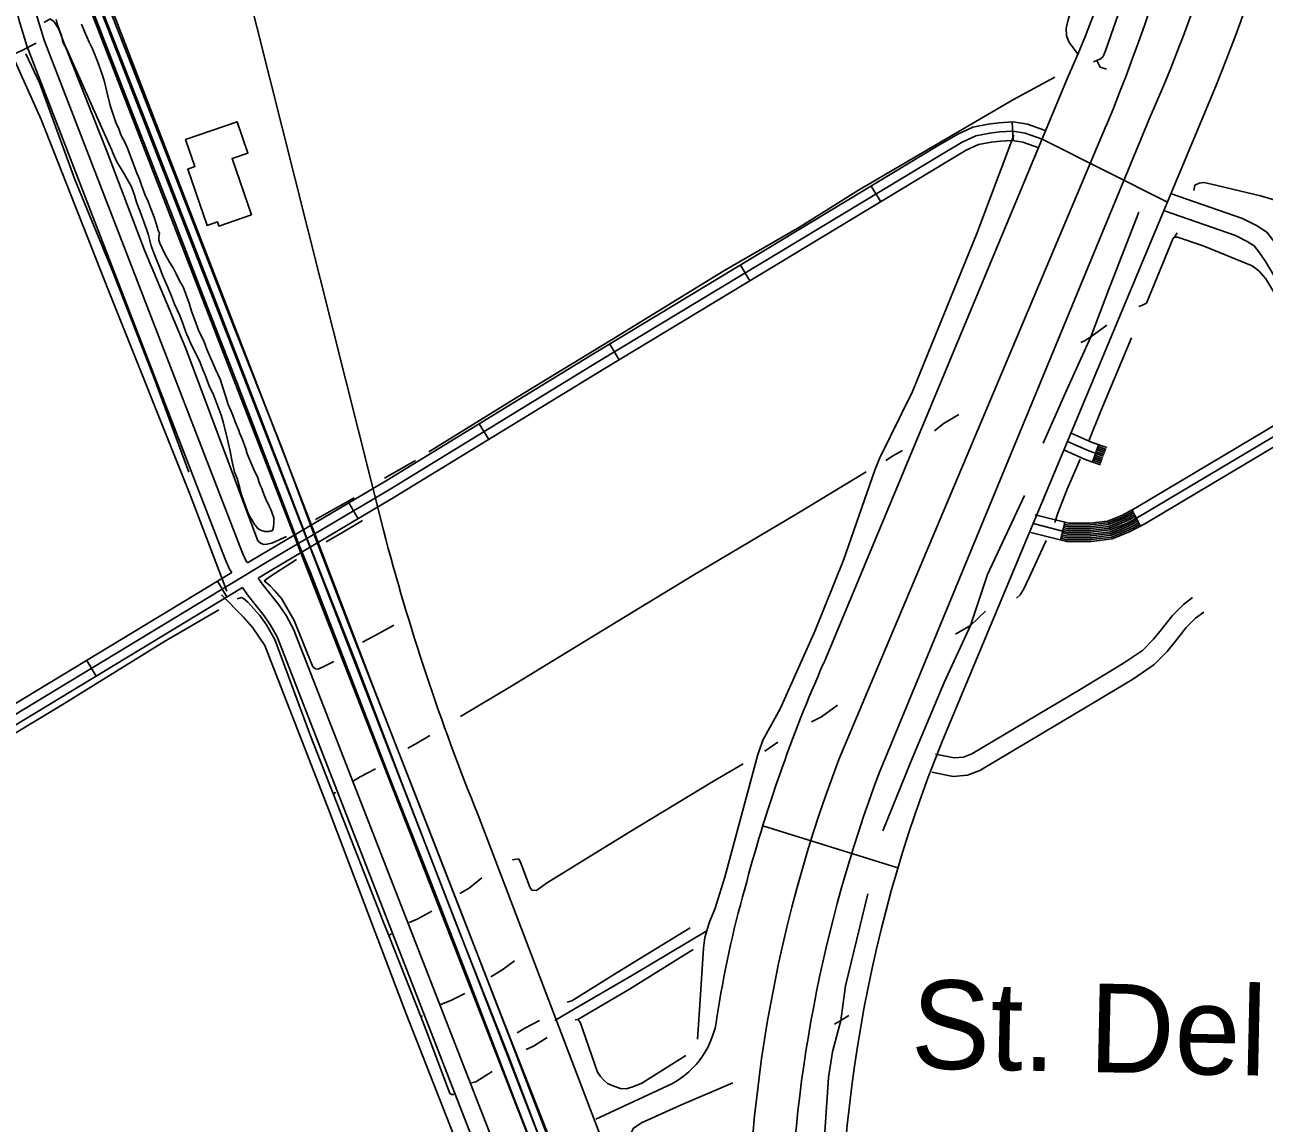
# Model space of a CAD drawing. Extents: x 3297753 to 3335611, y 652252 to 677623.
# Drawn here: x 3302520 to 3304548, y 670038 to 671835 of the extents above; entities that cross this region are included whole.
import ezdxf

# ---------------------------------------------------------------- set-up
doc = ezdxf.new("R2010")
doc.units = 0
for name, color, linetype in [('V-BLDG-OTLN', 7, 'Continuous'), ('V-DTCH-CNTR', 7, 'Continuous'), ('V-RAIL-TRAK', 7, 'Continuous'), ('V-ROAD-CNTR', 7, 'Continuous'), ('V-SITE-VEGE', 7, 'Continuous'), ('V-TOPO-GNAM-IDEN', 7, 'Continuous'), ('V-TOPO-SHOR', 7, 'Continuous')]:
    doc.layers.add(name, color=color, linetype=linetype)

msp = doc.modelspace()

# ---------------------------------------------------------------- linework, layer by layer
at = {"layer": 'V-BLDG-OTLN'}
msp.add_lwpolyline([(3302891.2, 671523.9), (3302859.4, 671615.8), (3302885.3, 671624.8), (3302867.7, 671675.9), (3302783.4, 671646.8), (3302798.6, 671602.6), (3302786.9, 671598.6), (3302818.7, 671506.3), (3302835.6, 671512.1), (3302837.8, 671505.5)], close=True, dxfattribs=at)
at = {"layer": 'V-DTCH-CNTR'}
for points in [[(3304244.1, 671785.6), (3304229, 671805.8), (3304224.6, 671816.7), (3304224.2, 671829.1), (3304227.2, 671843), (3304299.5, 672078.6), (3304340.8, 672243.1), (3304357.6, 672327.6), (3304367.6, 672385.1), (3304397.4, 672611.9), (3304404.4, 672725.7), (3304402.5, 672766.3), (3304397.4, 672822.7), (3304381.7, 672886.3), (3304375.8, 672900.6), (3304371.5, 672908), (3304359.4, 672920.7), (3304308.5, 672964), (3304301.4, 672972.1), (3304283.9, 672998.3)], [(3301862.2, 671467.5), (3302180.1, 671631), (3302468.1, 671771), (3302499.7, 671785.3), (3302515.6, 671792.4), (3302539, 671804.8)], [(3302499.7, 671785.3), (3302546.9, 671679.9), (3302657.1, 671400), (3302789.5, 671068.5), (3302850.9, 670908.2)], [(3304138.6, 671653.9), (3304078, 671493.1), (3303972.7, 671234.6), (3303918.8, 671125), (3303911.1, 671106.2), (3303859.7, 670958.7), (3303813.6, 670843.8), (3303756.1, 670715.5), (3303728, 670664.4), (3303721.6, 670647), (3303719.8, 670640.8), (3303665.8, 670440.3), (3303649.4, 670388.1), (3303640.4, 670367.2), (3303636, 670352.2), (3303632.9, 670341.5), (3303630.7, 670324.3), (3303624.5, 670231.2), (3303620.6, 670175.3)], [(3302842.1, 670902.3), (3302878.3, 670865.5), (3302893.3, 670848.1), (3302912.7, 670819), (3303018.6, 670547.3), (3303144, 670216.9), (3303265.4, 669907.8), (3303395.9, 669571.4), (3303462.9, 669403.2), (3303542.7, 669195.5), (3303547.3, 669180.4), (3303546.6, 669157), (3303533, 669058.1), (3303521.6, 669013)], [(3303636, 670352.2), (3303514.3, 670279.8), (3303420.9, 670225.4), (3303387.2, 670205.9)]]:
    msp.add_lwpolyline(points, dxfattribs=at)
at = {"layer": 'V-RAIL-TRAK'}
for points in [[(3302181.6, 673057.5), (3302229.8, 672933.1), (3302296.9, 672759.3), (3302374.4, 672560.5), (3302455, 672349.9), (3302535.3, 672147.1), (3302633.7, 671892), (3302728.1, 671651.1), (3302827.9, 671394.2), (3302937.3, 671109.7), (3302983.3, 670990.7), (3303061.7, 670791.9), (3303137.8, 670593.1), (3303225.7, 670365.7), (3303312.1, 670146.1), (3303400.2, 669915.1), (3303477.6, 669717.2), (3303551.6, 669527.1), (3303640.5, 669300.6), (3303710.4, 669119), (3303794.8, 668900.7), (3303880.9, 668677)], [(3303865.6, 668760.1), (3303793, 668948.4), (3303739.8, 669084.6), (3303721.9, 669124.8), (3303683.6, 669226.5), (3303609, 669421.9), (3303553, 669563.5), (3303502.7, 669694.7), (3303411, 669924.2), (3303320.1, 670159.8), (3303237.1, 670375.8), (3303155.6, 670584.1), (3303054.9, 670841.4), (3302995, 670997.5), (3302940.6, 671142.8), (3302854.9, 671358.3), (3302764.3, 671592.4), (3302665.5, 671843.8), (3302574.2, 672074.7), (3302480.7, 672320.3), (3302400.5, 672534.1), (3302313.6, 672755.6), (3302230.6, 672970.7), (3302196.1, 673060.4)], [(3303841.3, 668740.2), (3303767.3, 668931.7), (3303710.7, 669076.9), (3303696.6, 669112.1), (3303647.9, 669236.5), (3303572.8, 669433.9), (3303556.4, 669476.2), (3303519.6, 669571), (3303477.1, 669674.8), (3303404, 669864.5), (3303320.1, 670079.2), (3303246.5, 670271.6), (3303180.4, 670443.7), (3303116.4, 670604.7), (3303055.8, 670762.2), (3302987.7, 670938.8), (3302969.9, 670981.8), (3302932.6, 671079), (3302866.5, 671251), (3302811.4, 671392.1), (3302762.7, 671518.7), (3302691.1, 671703.9), (3302618.1, 671892.7)]]:
    msp.add_lwpolyline(points, dxfattribs=at)
at = {"layer": 'V-ROAD-CNTR'}
for p, q in [((3304137.4, 671645.7), (3304135.7, 671675.6)), ((3303920.6, 671545.2), (3303905.1, 671570.9)), ((3303706.7, 671415.9), (3303691.1, 671441.6)), ((3303492.7, 671286.7), (3303477.2, 671312.4)), ((3303279.4, 671156.3), (3303263.8, 671181.9)), ((3304277.2, 671147.6), (3304267, 671119.4)), ((3303065.5, 671026.6), (3303050.2, 671052.4)), ((3304331.5, 671041), (3304345.8, 671014.6)), ((3304222.1, 671020.9), (3304214.7, 670991.8)), ((3302850.9, 670898.7), (3302835.3, 670924.3)), ((3302637, 670769.2), (3302621.5, 670794.9))]:
    msp.add_line(p, q, dxfattribs=at)
for points in [[(3303107, 671007.8), (3302817.6, 672159), (3302659.4, 672783.7), (3302407.6, 673804.4), (3302220.1, 674556.3), (3302197.1, 674662.2)], [(3303929.7, 668588.8), (3303721.8, 669127.7), (3303498.9, 669709), (3303308.4, 670192.2), (3303092.6, 670746.3), (3302990.7, 671011.8), (3302616.9, 671979.1), (3302395, 672548.1), (3302140.6, 673200.8), (3301941.7, 673724), (3301858.4, 673934.7)], [(3306005.5, 663196.3), (3304715.5, 666525.6), (3304323.1, 667532.4), (3303700.3, 669143.4), (3302983.3, 670989.4), (3302517.9, 672183.2), (3302128.4, 673187.7), (3301925.1, 673723.4), (3301858.5, 673891.5)], [(3301858.5, 673843), (3302110.4, 673192.6), (3302969.1, 670977.7), (3303699.5, 669104.9), (3304312.1, 667521.8), (3304841.2, 666157.3), (3305391.9, 664734.2), (3306004.5, 663141.9)], [(3301853.3, 672053.9), (3302344.2, 672280.1), (3302370.6, 672286), (3302388.1, 672281.1), (3302400.7, 672272.5), (3302410.8, 672259.5), (3302424, 672232.3), (3302519.1, 671985.6), (3302526.7, 671962.8), (3302531.2, 671932.8), (3302534.3, 671904.9), (3302535.6, 671867.9), (3302539.6, 671851), (3302552, 671809.8), (3302875.9, 670971.9), (3302881.4, 670959.2), (3302884.8, 670954.3)], [(3301865.8, 672026.6), (3302353.8, 672251.5), (3302369.8, 672255.1), (3302375.2, 672253.6), (3302379.9, 672250.4), (3302385.2, 672243.6), (3302396.5, 672220.4), (3302490.9, 671975.5), (3302497.4, 671955.8), (3302501.4, 671928.9), (3302504.3, 671902.7), (3302505.7, 671863.9), (3302510.6, 671843.3), (3302523.6, 671800), (3302848.1, 670960.5), (3302855.1, 670944.4), (3302859.1, 670938.7)], [(3304226.8, 671748.8), (3303827.3, 670790.5)], [(3304468.9, 671734.1), (3304022.2, 670665)], [(3304189.6, 671661.7), (3304160.6, 671672), (3304137.6, 671675.8), (3304114.1, 671674.4), (3304096.5, 671672.3), (3304071.5, 671667.3), (3304046.8, 671656), (3304014.9, 671637.2), (3303452.5, 671297.5), (3303110.4, 671088), (3302907.3, 670967.9), (3302884.8, 670954.3)], [(3304359.7, 671680.4), (3303917.6, 670609.2)], [(3304184.6, 671647.5), (3304156.8, 671657.4), (3304136.8, 671660.7), (3304115.4, 671659.5), (3304098.9, 671657.5), (3304076.1, 671652.9), (3304053.8, 671642.7), (3304022.6, 671624.3), (3303460.3, 671284.7), (3303118.1, 671075.2), (3302915, 670955), (3301860.5, 670316.7)], [(3304289.7, 671669.7), (3303852.2, 670632.6)], [(3304179.6, 671633.4), (3304153.1, 671642.8), (3304136, 671645.6), (3304116.7, 671644.5), (3304101.3, 671642.7), (3304080.8, 671638.6), (3304060.7, 671629.4), (3304030.3, 671611.4), (3303468.1, 671271.8), (3303125.9, 671062.3), (3302922.7, 670942.2), (3302902, 670929.6)], [(3304389.8, 671544.6), (3304184.6, 671647.5)], [(3304814.2, 671065), (3304575.3, 671463.7), (3304565.3, 671478.7), (3304552.5, 671495.3), (3304535.3, 671506.4), (3304512.8, 671517.7), (3304394.7, 671558.8)], [(3304672.3, 671243.5), (3304550, 671447.6), (3304540.9, 671461.2), (3304531.9, 671472.9), (3304520.4, 671480.4), (3304501.1, 671490.1), (3304384.8, 671530.5)], [(3304169.9, 671018.6), (3304226.7, 671004.2), (3304264.1, 671004.6), (3304295.5, 671008.3), (3304322.6, 671019.1), (3304345.5, 671031.5), (3304692.9, 671238.3)], [(3304173.6, 671033.1), (3304228.5, 671019.3), (3304263.1, 671019.5), (3304291.7, 671022.9), (3304316.2, 671032.7), (3304338.1, 671044.6), (3304672.3, 671243.5)], [(3304166.3, 671004), (3304224.9, 670989.2), (3304265.1, 670989.6), (3304299.2, 670993.6), (3304329, 671005.5), (3304352.9, 671018.5), (3304687.7, 671217.7)], [(3304232.1, 671166.6), (3304266.4, 671151.5), (3304290.4, 671142.9)], [(3304226, 671152.9), (3304260.9, 671137.6), (3304285.3, 671128.8)], [(3304276.2, 671144.8), (3304289.4, 671140)], [(3304220, 671139.1), (3304255.3, 671123.7), (3304280.1, 671114.7)], [(3304269.1, 671125.1), (3304282.2, 671120.3)], [(3304270.1, 671127.9), (3304283.2, 671123.1)], [(3304271.1, 671130.7), (3304284.2, 671125.9)], [(3304272.1, 671133.5), (3304285.3, 671128.8)], [(3304273.2, 671136.3), (3304286.3, 671131.6)], [(3304274.2, 671139.2), (3304287.3, 671134.4)], [(3304275.2, 671142), (3304288.3, 671137.2)], [(3304268, 671122.2), (3304281.2, 671117.5)], [(3304216.9, 671000.5), (3304226, 670998.2), (3304264.5, 670998.6), (3304296.9, 671002.4), (3304325.2, 671013.7), (3304341.5, 671022.5)], [(3304217.7, 671003.4), (3304226.3, 671001.2), (3304264.3, 671001.6), (3304296.2, 671005.4), (3304323.9, 671016.4), (3304340.1, 671025.2)], [(3304218.4, 671006.3), (3304226.7, 671004.2), (3304264.1, 671004.6), (3304295.5, 671008.3), (3304322.6, 671019.1), (3304338.6, 671027.8)], [(3304219.1, 671009.2), (3304227, 671007.2), (3304263.9, 671007.5), (3304294.7, 671011.2), (3304321.3, 671021.9), (3304337.2, 671030.5)], [(3304219.9, 671012.1), (3304227.4, 671010.2), (3304263.7, 671010.5), (3304294, 671014.2), (3304320.1, 671024.6), (3304335.8, 671033.1)], [(3304220.6, 671015.1), (3304227.8, 671013.2), (3304263.5, 671013.5), (3304293.2, 671017.1), (3304318.8, 671027.3), (3304334.4, 671035.7)], [(3304221.4, 671018), (3304228.1, 671016.3), (3304263.3, 671016.5), (3304292.5, 671020), (3304317.5, 671030), (3304332.9, 671038.4)], [(3304215.5, 670994.7), (3304225.2, 670992.2), (3304264.9, 670992.6), (3304298.4, 670996.6), (3304327.7, 671008.3), (3304344.4, 671017.3)], [(3304216.2, 670997.6), (3304225.6, 670995.2), (3304264.7, 670995.6), (3304297.7, 670999.5), (3304326.4, 671011), (3304342.9, 671019.9)], [(3302859.1, 670938.7), (3301860.5, 670334.2)], [(3302902, 670929.6), (3302908.6, 670920.3), (3302935.9, 670885.8), (3302947.7, 670868.5), (3302960.1, 670846.1), (3303638.4, 669105)], [(3302876.3, 670914.1), (3301860.5, 670299.2)], [(3302876.3, 670914.1), (3302884.5, 670902.4), (3302911.7, 670868), (3302922.1, 670852.7), (3302932.9, 670833.4), (3303612.4, 669089.2)], [(3304430.7, 670897.7), (3304416.1, 670886.4), (3304398, 670868.6), (3304379.5, 670845.1), (3304367.1, 670829.6), (3304348.8, 670811.1), (3304318, 670790.1), (3304247, 670747.5), (3304069.7, 670641.8), (3304056.1, 670636.5), (3304041, 670635.4), (3304010, 670641.5)], [(3304449.1, 670874), (3304435.9, 670863.8), (3304420.4, 670848.5), (3304403, 670826.5), (3304389.5, 670809.7), (3304368.1, 670787.9), (3304334.2, 670764.8), (3304262.4, 670721.8), (3304082.9, 670614.8), (3304062.9, 670607), (3304039.2, 670605.2), (3304004.2, 670612.1)], [(3303526.3, 669848.3), (3303261.8, 670541.9)], [(3303727.6, 670524), (3303948.8, 670455.5)], [(3303579, 670102.1), (3303454.4, 670044.5)]]:
    msp.add_lwpolyline(points, dxfattribs=at)
for centre, radius, start, end in [((3301923.9, 672761.6), 2665, 336.0643, 356.8078), ((3301815.2, 672812.6), 2864.5, 337.8829, 356.1146), ((3301352.1, 672880.3), 3177.3, 337.6024, 354.4678), ((3301948, 672750.8), 2489.4, 336.2654, 354.3553), ((3306797.6, 671975.8), 3815.5, 194.6969, 202.0738), ((3306054.5, 669805.5), 2435.3, 156.1423, 165.3625), ((3306144.2, 669804.4), 2289.9, 157.9226, 184.037), ((3305997.7, 669817.5), 2295.2, 159.1973, 184.4635), ((3306068.5, 669801.1), 2297.7, 159.4088, 179.1328), ((3305328.3, 669958.2), 1694.5, 164.1527, 171.4384), ((3303509.3, 670228.7), 144.6, 298.84, 352.7293)]:
    msp.add_arc(centre, radius, start, end, dxfattribs=at)
at = {"layer": 'V-SITE-VEGE'}
for points in [[(3302895.2, 671107.3), (3302901.7, 671093.4), (3302903.2, 671087.3), (3302906.1, 671080.7), (3302908, 671075.9), (3302911.3, 671066.8), (3302914.7, 671058.9), (3302920.8, 671046.3), (3302922.7, 671042), (3302927.5, 671028), (3302927.7, 671020.5), (3302927, 671013), (3302925.5, 671007.2), (3302919.3, 671005.7), (3302913.2, 671005.5), (3302906, 671008), (3302901.5, 671010.9), (3302895.1, 671018.7), (3302893.7, 671021.3), (3302887.2, 671031.7), (3302884.8, 671038.7), (3302878.6, 671054.8), (3302874.3, 671067.5), (3302872.2, 671076.7), (3302867.4, 671092.4), (3302863.5, 671102.9), (3302859, 671122.6), (3302856.3, 671137.1), (3302851.3, 671158.5), (3302844.8, 671185.2), (3302841.4, 671196.2), (3302835.1, 671213.6), (3302828.4, 671231.1), (3302822.4, 671242.4), (3302815.7, 671260.2), (3302810.9, 671271.6), (3302807.1, 671282), (3302800.5, 671296), (3302793, 671310.7), (3302783.6, 671331.6), (3302778.2, 671347.8), (3302773.4, 671360.4), (3302765.4, 671377.4), (3302760.2, 671390.5), (3302754.5, 671403.6), (3302745.5, 671424.9), (3302739.8, 671439.7), (3302731.7, 671460.2), (3302726.9, 671472.9), (3302722.4, 671490.4), (3302719.5, 671500.4), (3302708.4, 671530.5), (3302703.7, 671542.8), (3302701.2, 671550.2), (3302699.7, 671555.9), (3302696.9, 671563.7), (3302694.5, 671570.7), (3302685.6, 671585.9), (3302682.4, 671592), (3302670.8, 671610.6), (3302664.2, 671625.4), (3302662.7, 671629.8), (3302648.1, 671662.4), (3302588.1, 671796.9), (3302585.8, 671800), (3302582.5, 671806), (3302580, 671817), (3302577.1, 671825.3), (3302573.8, 671834.4), (3302571.7, 671843.6)], [(3302613, 671835.6), (3302617.7, 671823.8), (3302625.7, 671806.4), (3302630.9, 671795.6), (3302637.6, 671779), (3302641.9, 671767.6), (3302645.7, 671756.7), (3302650.1, 671743.6), (3302655.1, 671722.6), (3302659.7, 671702.9), (3302663.6, 671691.1), (3302669.3, 671674.9), (3302674, 671664.5), (3302677.4, 671654.9), (3302684.9, 671640.6), (3302688.7, 671631.4), (3302694.4, 671617), (3302703.5, 671591.7), (3302707.8, 671582.1), (3302711.2, 671572.1), (3302717.4, 671556), (3302722.1, 671545.5), (3302725.9, 671535), (3302732.1, 671519.8), (3302737.1, 671502.3), (3302738.5, 671497.9), (3302740.8, 671493.6), (3302739.7, 671486.5), (3302739.4, 671482.1), (3302741.3, 671477.3), (3302749.3, 671459.9), (3302756.8, 671446.4), (3302763.2, 671436.9), (3302767.9, 671427.3), (3302773.6, 671414.7), (3302779.2, 671406), (3302789.2, 671379.4), (3302793.1, 671366.3), (3302799.9, 671347.1), (3302804.6, 671334.9), (3302813.6, 671315.8), (3302818.8, 671302.2), (3302826.9, 671283.9), (3302831.6, 671272.6), (3302839.6, 671254.8), (3302843.5, 671243), (3302849.3, 671225.9), (3302853.2, 671213.7), (3302860.8, 671195.8), (3302864.6, 671185.4), (3302870.3, 671171), (3302871.3, 671167), (3302876, 671157.5), (3302881.8, 671140.9), (3302883.8, 671132.6), (3302895.2, 671107.3)]]:
    msp.add_lwpolyline(points, dxfattribs=at)
at = {"layer": 'V-TOPO-SHOR'}
for p, q in [((3304279.9, 671765.2), (3304274.2, 671776.4)), ((3304290, 671762.1), (3304279.9, 671765.2)), ((3304405.8, 671494.5), (3304401.2, 671487.3)), ((3304246.8, 671123.9), (3304225.6, 671074.9)), ((3303159.5, 671122.1), (3303108.9, 671092.8)), ((3303028.3, 670579.3), (3303025.5, 670575.3)), ((3303899.3, 670413.1), (3303862.9, 670262.3)), ((3303120.1, 670347.3), (3303115.7, 670345.1)), ((3303862.9, 670262.3), (3303855.2, 670205.8)), ((3303171.1, 670213.5), (3303168, 670212.3))]:
    msp.add_line(p, q, dxfattribs=at)
for points in [[(3304477, 673033.9), (3304483.8, 672929.3), (3304483.9, 672839.4), (3304483.9, 672822.9), (3304482.3, 672713.3), (3304477, 672624.9), (3304467.7, 672532.6), (3304442.8, 672363.9), (3304419.3, 672232.1), (3304389.4, 672113.7), (3304350.1, 671969.4), (3304288.7, 671793.8), (3304284.5, 671783), (3304280.5, 671778.8), (3304274.2, 671776.4), (3304269, 671774.3)], [(3302948.6, 670997.4), (3302924.5, 670986.8), (3302916.3, 670984.8), (3302911.2, 670984.6), (3302906, 670986.6), (3302902.4, 670989.2), (3302901.4, 670990.5), (3302857.8, 671107), (3302783.6, 671305), (3302716, 671466.2), (3302654.2, 671628.1), (3302588.1, 671795.8), (3302575.5, 671828.7), (3302568.3, 671839.5), (3302562.3, 671843.8), (3302561, 671844.1), (3302554.2, 671840.1), (3302551.8, 671838.7)], [(3302788.8, 671103), (3302731.7, 671256.5), (3302665.2, 671427.6), (3302601.9, 671581.7), (3302544.8, 671738.6), (3302521.7, 671787.4)], [(3304205.5, 671748.8), (3304137.9, 671712.4), (3304027.9, 671648.1), (3303884.1, 671564.2)], [(3304620.2, 671532.1), (3304541.9, 671554.9), (3304461.6, 671574.2), (3304449.5, 671576.9), (3304441.6, 671575.7), (3304434.8, 671572.4), (3304433, 671563.7)], [(3303884.1, 671564.2), (3303788, 671503.6), (3303664.1, 671432)], [(3304343, 671528.2), (3304294.8, 671404.8), (3304264.4, 671324.3)], [(3304648.1, 671256.6), (3304590.2, 671353.8), (3304550.9, 671419.3), (3304539.5, 671432), (3304528.3, 671440.2), (3304448, 671472.9), (3304406.4, 671487.5), (3304401.2, 671487.3), (3304399.2, 671485.5), (3304355.3, 671379.2), (3304349.2, 671375.9), (3304342.8, 671374)], [(3303664.1, 671432), (3303479.9, 671319.4), (3303324.4, 671224.5), (3303181.1, 671136.1)], [(3304290.4, 671343.2), (3304264.4, 671324.3), (3304262.9, 671323.2), (3304253.8, 671317.8), (3304248, 671315.2)], [(3304186.5, 671150), (3304224.4, 671236.3), (3304264.4, 671324.3)], [(3304330.9, 671322.5), (3304281.5, 671204.3), (3304261, 671153.9)], [(3304048.5, 671197), (3304024.6, 671182.9), (3304008.8, 671170.4)], [(3303956.5, 671138.3), (3303941.7, 671130), (3303929.2, 671122.1)], [(3303896.8, 671103.6), (3303783.4, 671034.7), (3303613, 670933.5), (3303465.2, 670844), (3303315.5, 670752.3), (3303233.2, 670702.9)], [(3304156, 671064.6), (3304095.3, 670935.4), (3304067.3, 670851.8)], [(3304225.6, 671074.9), (3304210.6, 671036), (3304205.5, 671020.4)], [(3303059, 671060.8), (3303010.3, 671033.6), (3302996.1, 671025.6)], [(3303072.9, 671024), (3303036.4, 671001.9), (3303013.5, 670988.6)], [(3304191.6, 670990.8), (3304163.5, 670930.5), (3304154.2, 670910.7), (3304148.6, 670902.3), (3304142.9, 670896.9)], [(3302964.9, 670960), (3302923.4, 670933.4), (3302911.6, 670925.1)], [(3303026.1, 670793.2), (3303007.2, 670783.7), (3302999.7, 670780.7), (3302995.6, 670781.3), (3302991.3, 670784.6), (3302961, 670859.9), (3302940, 670896.1), (3302928.6, 670909.1), (3302921.8, 670916.8), (3302911.6, 670925.1)], [(3303222.2, 670084.9), (3303218.4, 670084.8), (3303215.7, 670086.5), (3303179.1, 670183.9), (3303168, 670212.3), (3303115.7, 670345.1), (3303106.7, 670367.9), (3303036.2, 670547.8), (3302987.9, 670671.4), (3302929.3, 670829), (3302915.9, 670853.3), (3302904.8, 670868.5), (3302884.9, 670890.2), (3302878.2, 670896.2), (3302874.8, 670897.8), (3302867.6, 670895.5)], [(3302837.6, 670877.5), (3302747.8, 670825.4), (3302581.5, 670722.3), (3302427, 670629.4), (3302301.5, 670554), (3302125.4, 670447.1), (3301971.2, 670353.6), (3301862.9, 670288.4)], [(3304092, 670875.2), (3304067.3, 670851.8), (3304043, 670838)], [(3303123.9, 670852.4), (3303092.5, 670835.3), (3303072.9, 670824.8)], [(3303924.1, 670516.2), (3303971.1, 670631.6), (3304024.7, 670758.5), (3304067.3, 670851.8)], [(3303850, 670721.8), (3303823.8, 670702.8), (3303807.6, 670694.4)], [(3303182.8, 670672.1), (3303159.9, 670658.4), (3303146.7, 670651.2)], [(3303752.2, 670661.2), (3303731, 670646.5), (3303731, 670646.4)], [(3303093.8, 670617.7), (3303069.1, 670604.6), (3303058, 670598.1)], [(3303695.6, 670625.7), (3303647.3, 670597.3), (3303507.6, 670512.8), (3303373.7, 670430.6), (3303357.3, 670418.4), (3303350, 670419.2), (3303346.5, 670423.9), (3303331.2, 670464.7), (3303327.9, 670470.1), (3303318.4, 670468.4)], [(3303268.1, 670438.9), (3303247, 670422.5), (3303232.1, 670413.5)], [(3303186.3, 670384.6), (3303162, 670371.6), (3303149.1, 670366)], [(3303608.7, 670357.2), (3303489.3, 670284.3), (3303415.5, 670238.1), (3303407.7, 670235.5)], [(3303613.9, 670322.1), (3303509.4, 670257.2), (3303425, 670207.3)], [(3303321.2, 670303.5), (3303300.8, 670288.1), (3303282.5, 670277.3)], [(3303240.1, 670249.9), (3303218.1, 670239), (3303201.1, 670231.9)], [(3303868.4, 670214.1), (3303855.2, 670205.8), (3303845.2, 670200)], [(3303362.5, 670206), (3303338.5, 670193), (3303326, 670185.7)], [(3303601.8, 670148.7), (3303529.7, 670103), (3303514.8, 670097), (3303504.2, 670094), (3303494.9, 670094.7), (3303484.2, 670098.5), (3303473.7, 670102.7), (3303467.8, 670108), (3303462.1, 670114), (3303457.1, 670121.1), (3303428.9, 670203.3), (3303425, 670207.3), (3303420.5, 670206.9)], [(3303820.1, 669815.7), (3303821.4, 669909.9), (3303835, 670112.5), (3303841.6, 670154.6), (3303855.2, 670205.8)], [(3303375, 670177.7), (3303352.4, 670164), (3303340.6, 670158.5)], [(3303285, 670122.5), (3303258, 670105.2), (3303250.9, 670104)], [(3303678.4, 670103.7), (3303591.9, 670066.5), (3303529.2, 670038.6), (3303515.4, 670028.9), (3303510.3, 670016), (3303507.2, 670004.3), (3303505.1, 669995.3), (3303500.4, 669990.3)]]:
    msp.add_lwpolyline(points, dxfattribs=at)

# ---------------------------------------------------------------- texts
at = {"layer": 'V-TOPO-GNAM-IDEN'}
msp.add_text('St. Delphine', height=145, rotation=358.7818, dxfattribs=at).set_placement((3303969.2, 670127.8))

doc.saveas('drawing.dxf')
